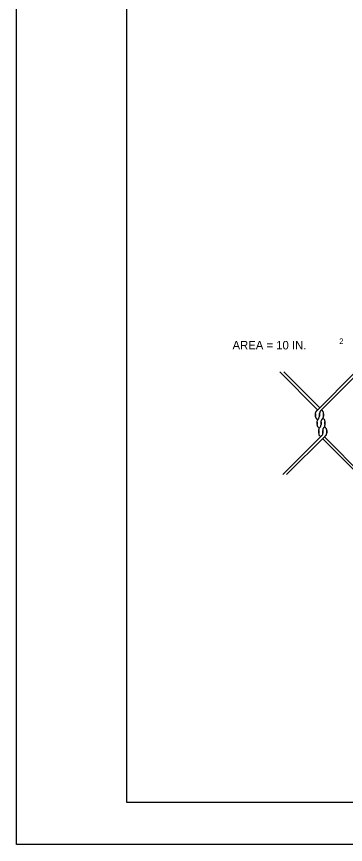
# Model space of a CAD drawing. Extents: x 3 to 3592, y -602 to 1171.
# Drawn here: x 2.5 to 119.2, y -17.2 to 276.1 of the extents above; entities that cross this region are included whole.
import ezdxf

# ---------------------------------------------------------------- set-up
doc = ezdxf.new("R2010")
doc.units = 0
for name, color, linetype in [('1', 7, 'Continuous'), ('3', 7, 'Continuous'), ('P', 7, 'Continuous'), ('PLT-BNDY', 7, 'Continuous')]:
    doc.layers.add(name, color=color, linetype=linetype)

msp = doc.modelspace()

# ---------------------------------------------------------------- linework, layer by layer
at = {"layer": '1'}
msp.add_lwpolyline([(827.51, -2.17), (827.51, 561.83), (41.51, 561.83), (41.51, -2.17), (827.51, -2.17), (827.51, 24.19), (627.51, 24.19), (627.51, 88.87), (827.51, 88.87), (827.51, 117.83), (627.51, 117.83), (627.51, -2.17), (706.31, -2.17), (706.31, 24.19), (706.31, -2.17), (783.31, -2.17), (783.31, 24.19), (783.31, 11.88), (827.51, 11.88)], dxfattribs=at)
at = {"layer": 'P'}
for points in [[(109.31, 136.79), (95.9, 150.2)], [(110.02, 137.6), (97.32, 150.2)], [(109, 136.48), (122.72, 150.2)], [(110.32, 136.48), (124.09, 150.15)], [(109, 136.48), (108.9, 136.38), (108.8, 136.28), (108.8, 136.18), (108.7, 136.08), (108.6, 135.98), (108.6, 135.77), (108.5, 135.67), (108.5, 135.47)], [(108.6, 134.65), (108.6, 135.47)], [(108.6, 135.37), (108.6, 134.55)], [(110.43, 136.48), (110.32, 136.38), (110.32, 136.28), (110.22, 136.18), (110.12, 136.08), (110.12, 135.98), (110.12, 135.77), (110.02, 135.67), (110.02, 135.47)], [(110.02, 134.65), (110.02, 135.47)], [(110.02, 134.65), (110.02, 135.47)], [(110.02, 135.37), (110.02, 134.55)], [(110.02, 135.37), (110.02, 134.55)], [(111.04, 136.48), (110.73, 136.79)], [(111.44, 135.47), (111.44, 135.67), (111.44, 135.77), (111.44, 135.98), (111.34, 136.08), (111.24, 136.18), (111.14, 136.28), (111.14, 136.38), (111.04, 136.48)], [(111.44, 134.65), (111.44, 135.47)], [(111.44, 135.37), (111.44, 134.55)], [(108.5, 134.55), (108.5, 134.45), (108.6, 134.25), (108.6, 134.15), (108.7, 133.94), (108.8, 133.94), (108.8, 133.74), (108.9, 133.64), (109, 133.54)], [(109, 133.54), (109.31, 133.23)], [(109.61, 133.54), (109.51, 133.33), (109.41, 133.33), (109.31, 133.13), (109.31, 133.13), (109.21, 132.93), (109.21, 132.83), (109.11, 132.62), (109.11, 132.52)], [(109.21, 131.71), (109.21, 132.52)], [(109.21, 132.42), (109.21, 131.61)], [(109.61, 133.54), (109.61, 133.64), (109.72, 133.74), (109.82, 133.94), (109.82, 133.94), (109.92, 134.15), (109.92, 134.25), (110.02, 134.45), (110.02, 134.55)], [(110.93, 133.54), (110.83, 133.33), (110.83, 133.33), (110.73, 133.13), (110.63, 133.13), (110.63, 132.93), (110.63, 132.83), (110.53, 132.62), (110.53, 132.52)], [(110.63, 131.71), (110.63, 132.52)], [(110.63, 131.71), (110.63, 132.52)], [(110.63, 132.42), (110.63, 131.61)], [(110.63, 132.42), (110.63, 131.61)], [(111.04, 133.54), (111.14, 133.64), (111.14, 133.74), (111.24, 133.94), (111.34, 133.94), (111.44, 134.15), (111.44, 134.25), (111.44, 134.45), (111.44, 134.55)], [(111.54, 133.44), (111.34, 133.74)], [(112.05, 132.52), (112.05, 132.62), (111.95, 132.83), (111.95, 132.93), (111.95, 133.13), (111.85, 133.13), (111.75, 133.33), (111.65, 133.33), (111.65, 133.54)], [(111.95, 131.71), (111.95, 132.52)], [(111.95, 132.42), (111.95, 131.61)], [(109.11, 131.51), (109.11, 131.4), (109.21, 131.3), (109.21, 131.1), (109.31, 131), (109.31, 130.9), (109.41, 130.79), (109.51, 130.69), (109.61, 130.49)], [(110.12, 130.49), (110.02, 130.39), (109.92, 130.29), (109.82, 130.18), (109.82, 130.08), (109.72, 129.98), (109.72, 129.78), (109.61, 129.68), (109.61, 129.47)], [(109.61, 130.49), (109.82, 130.29)], [(109.72, 128.66), (109.72, 129.47)], [(109.72, 129.47), (109.72, 128.46)], [(110.12, 130.49), (110.22, 130.69), (110.32, 130.79), (110.32, 130.9), (110.43, 131), (110.53, 131.1), (110.53, 131.3), (110.63, 131.4), (110.63, 131.51)], [(111.54, 130.49), (111.44, 130.39), (111.44, 130.29), (111.34, 130.18), (111.24, 130.08), (111.14, 129.98), (111.14, 129.78), (111.14, 129.68), (111.14, 129.47)], [(111.14, 128.66), (111.14, 129.47)], [(111.14, 128.66), (111.14, 129.47)], [(111.14, 129.47), (111.14, 128.46)], [(111.14, 129.47), (111.14, 128.46)], [(111.65, 130.49), (111.65, 130.69), (111.75, 130.79), (111.85, 130.9), (111.95, 131), (111.95, 131.1), (111.95, 131.3), (112.05, 131.4), (112.05, 131.51)], [(112.15, 130.49), (111.85, 130.79)], [(112.56, 129.47), (112.56, 129.68), (112.46, 129.78), (112.46, 129.98), (112.46, 130.08), (112.36, 130.18), (112.26, 130.29), (112.15, 130.39), (112.15, 130.49)], [(112.56, 128.66), (112.56, 129.47)], [(112.56, 129.47), (112.56, 128.46)], [(97.02, 113.83), (110.73, 127.54)], [(98.34, 113.83), (112.15, 127.54)], [(109.61, 128.56), (109.61, 128.46), (109.72, 128.25), (109.72, 128.15), (109.82, 127.95), (109.82, 127.85), (109.92, 127.75), (110.02, 127.64), (110.12, 127.54)], [(110.12, 127.54), (110.32, 127.34)], [(110.73, 127.54), (110.83, 127.64), (110.83, 127.75), (110.93, 127.85), (111.04, 127.95), (111.14, 128.15), (111.14, 128.25), (111.14, 128.46), (111.14, 128.56)], [(111.14, 126.53), (123.94, 113.73)], [(111.85, 127.14), (125.46, 113.42)], [(112.15, 127.54), (112.15, 127.64), (112.26, 127.75), (112.36, 127.85), (112.46, 127.95), (112.46, 128.15), (112.46, 128.25), (112.56, 128.46), (112.56, 128.56)]]:
    msp.add_lwpolyline(points, dxfattribs=at)
at = {"layer": 'PLT-BNDY'}
msp.add_lwpolyline([(2.51, 576.83), (843.51, 576.83), (843.51, -17.17), (2.51, -17.17)], close=True, dxfattribs=at)

# ---------------------------------------------------------------- texts
at = {"layer": '3'}
for s, height, p in [('2', 2, (117.01, 160.07)), ('AREA = 10 IN. ', 3, (79.15, 158.18))]:
    msp.add_text(s, height=height, dxfattribs=at).set_placement(p)

doc.saveas('drawing.dxf')
